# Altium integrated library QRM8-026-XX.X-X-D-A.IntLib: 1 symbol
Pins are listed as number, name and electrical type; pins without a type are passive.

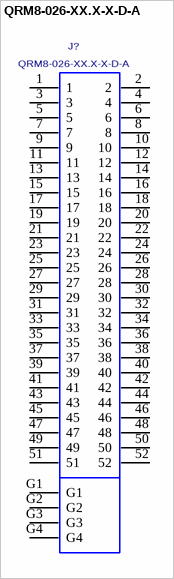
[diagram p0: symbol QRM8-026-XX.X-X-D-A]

## QRM8-026-XX.X-X-D-A
designator J?
.8mm Q-Rate Terminal Assembly.; MANUFACTURER: SAMTEC
footprint QRM8-026-XX.X-X-D-A
pins: 1, 2, 3, 4, 5, 6, 7, 8, 9, 10, 11, 12, 13, 14, 15, 16, 17, 18, 19, 20, 21, 22, 23, 24, 25, 26, 27, 28, 29, 30, 31, 32, 33, 34, 35, 36, 37, 38, 39, 40, 41, 42, 43, 44, 45, 46, 47, 48, 49, 50, 51, 52, G1, G2, G3, G4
